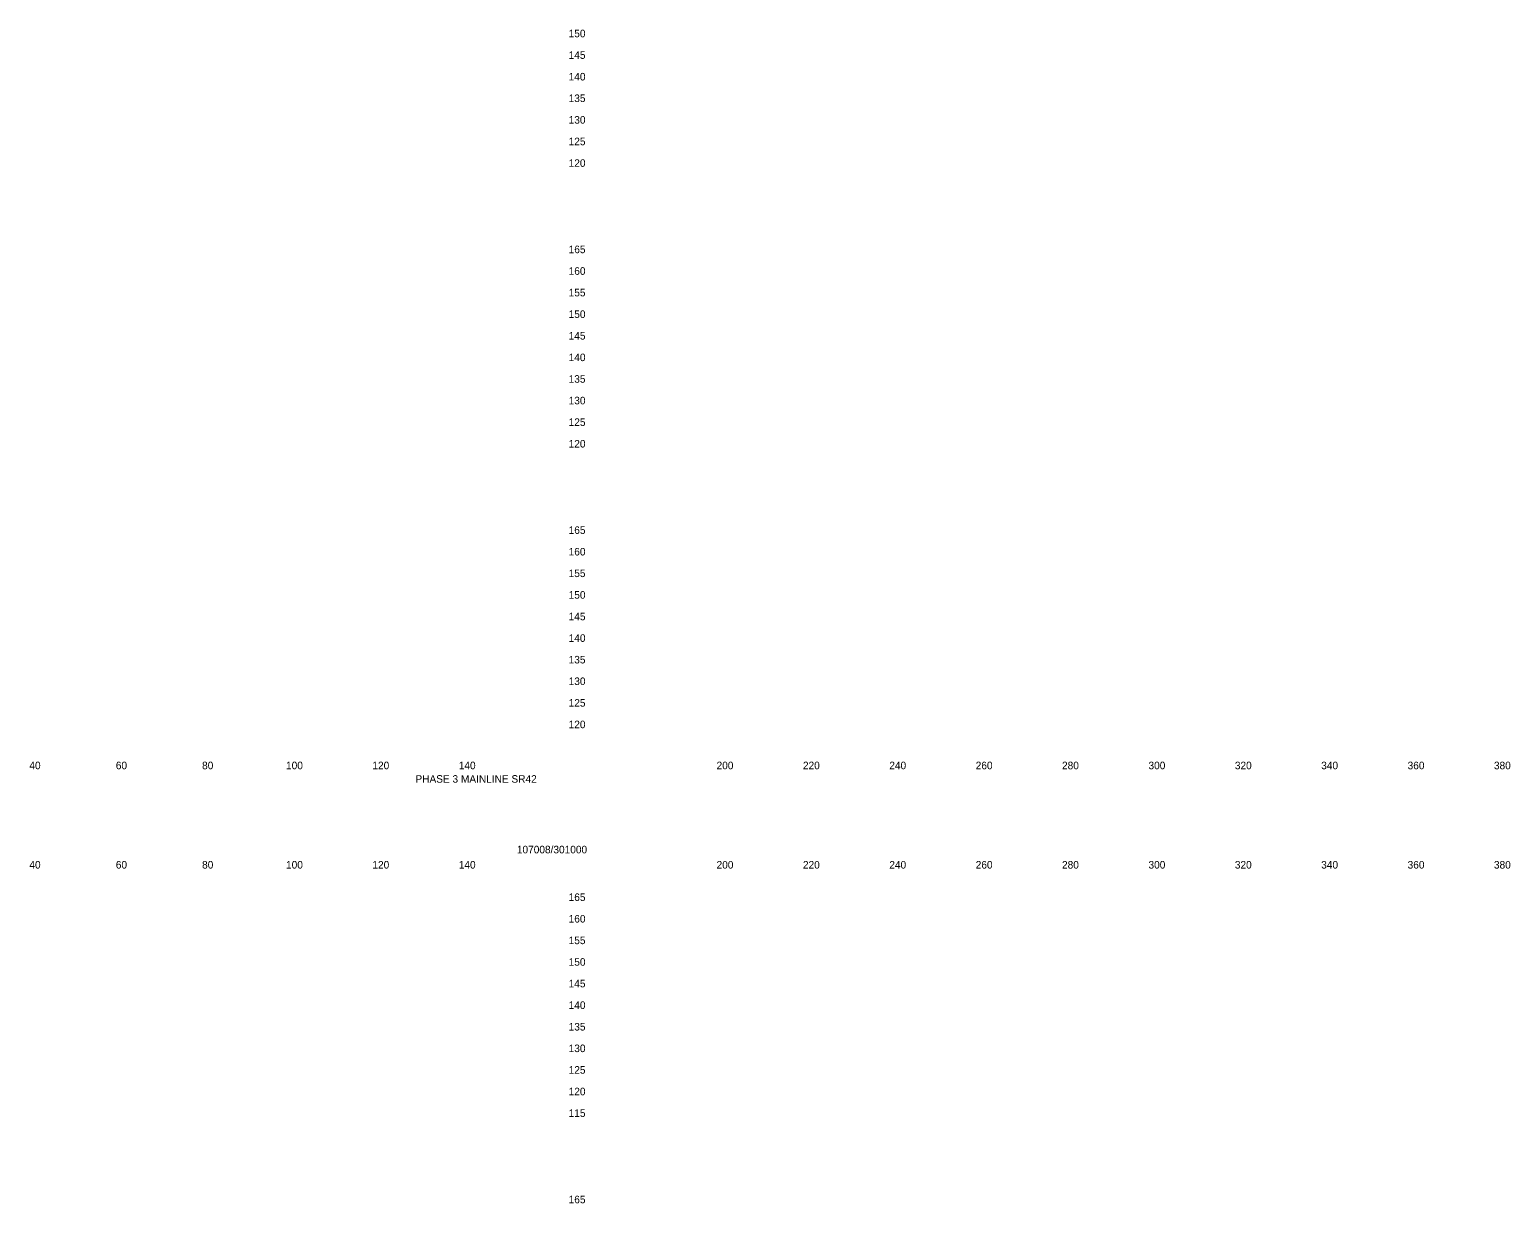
# Model space of a CAD drawing. Extents: x 21281 to 22024, y 6472 to 15198.
# Drawn here: x 21681.3 to 22024.2, y 14654.8 to 14926.6 of the extents above; entities that cross this region are included whole.
import ezdxf

# ---------------------------------------------------------------- set-up
doc = ezdxf.new("R2010")
doc.units = 0
doc.layers.add('Draft_XS_Grid', color=7, linetype='Continuous')
doc.layers.add('Draft_XS_Text', color=7, linetype='Continuous')

msp = doc.modelspace()

# ---------------------------------------------------------------- texts
at = {"layer": 'Draft_XS_Grid'}
for s, p in [('  150  ', (21804.84, 14924.84)), ('  145  ', (21804.84, 14919.84)), ('  140  ', (21804.84, 14914.84)), ('  135  ', (21804.84, 14909.84)), ('  130  ', (21804.84, 14904.84)), ('  125  ', (21804.84, 14899.84)), ('  120  ', (21804.84, 14894.84)), ('  165  ', (21804.84, 14874.84)), ('  160  ', (21804.84, 14869.84)), ('  155  ', (21804.84, 14864.84)), ('  150  ', (21804.84, 14859.84)), ('  145  ', (21804.84, 14854.84)), ('  140  ', (21804.84, 14849.84)), ('  135  ', (21804.84, 14844.84)), ('  130  ', (21804.84, 14839.84)), ('  125  ', (21804.84, 14834.84)), ('  120  ', (21804.84, 14829.84)), ('  165  ', (21804.84, 14809.84)), ('  160  ', (21804.84, 14804.84)), ('  155  ', (21804.84, 14799.84)), ('  150  ', (21804.84, 14794.84)), ('  145  ', (21804.84, 14789.84)), ('  140  ', (21804.84, 14784.84)), ('  135  ', (21804.84, 14779.84)), ('  130  ', (21804.84, 14774.84)), ('  125  ', (21804.84, 14769.84)), ('  120  ', (21804.84, 14764.84)), ('  165  ', (21804.84, 14724.84)), ('  160  ', (21804.84, 14719.84)), ('  155  ', (21804.84, 14714.84)), ('  150  ', (21804.84, 14709.84)), ('  145  ', (21804.84, 14704.84)), ('  140  ', (21804.84, 14699.84)), ('  135  ', (21804.84, 14694.84)), ('  130  ', (21804.84, 14689.84)), ('  125  ', (21804.84, 14684.84)), ('  120  ', (21804.84, 14679.84)), ('  115  ', (21804.84, 14674.84)), ('  165  ', (21804.84, 14654.84))]:
    msp.add_text(s, height=1.75, dxfattribs=at).set_placement(p)
at = {"layer": 'Draft_XS_Text'}
for s, p in [('  40  ', (21679.95, 14755.34)), ('  60  ', (21699.97, 14755.34)), ('  80  ', (21719.95, 14755.34)), ('  100  ', (21739.39, 14755.34)), ('  120  ', (21759.39, 14755.34)), ('  140  ', (21779.39, 14755.34)), ('  200  ', (21839.1, 14755.34)), ('  220  ', (21859.1, 14755.34)), ('  240  ', (21879.1, 14755.34)), ('  260  ', (21899.11, 14755.34)), ('  280  ', (21919.1, 14755.34)), ('  300  ', (21939.13, 14755.34)), ('  320  ', (21959.13, 14755.34)), ('  340  ', (21979.13, 14755.34)), ('  360  ', (21999.14, 14755.34)), ('  380  ', (22019.13, 14755.34)), ('PHASE 3 MAINLINE SR42', (21770.66, 14752.22)), ('107008/301000', (21794.15, 14735.87)), ('  40  ', (21679.95, 14732.34)), ('  60  ', (21699.97, 14732.34)), ('  80  ', (21719.95, 14732.34)), ('  100  ', (21739.39, 14732.34)), ('  120  ', (21759.39, 14732.34)), ('  140  ', (21779.39, 14732.34)), ('  200  ', (21839.1, 14732.34)), ('  220  ', (21859.1, 14732.34)), ('  240  ', (21879.1, 14732.34)), ('  260  ', (21899.11, 14732.34)), ('  280  ', (21919.1, 14732.34)), ('  300  ', (21939.13, 14732.34)), ('  320  ', (21959.13, 14732.34)), ('  340  ', (21979.13, 14732.34)), ('  360  ', (21999.14, 14732.34)), ('  380  ', (22019.13, 14732.34))]:
    msp.add_text(s, height=1.75, dxfattribs=at).set_placement(p)

doc.saveas('drawing.dxf')
